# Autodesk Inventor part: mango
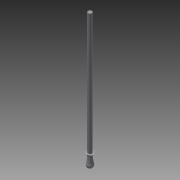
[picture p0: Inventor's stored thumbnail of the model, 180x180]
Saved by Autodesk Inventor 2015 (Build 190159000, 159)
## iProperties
Created: 2016-05
Part Number: mango
Material: Genérico
Document SubType Name: Modeling
Designer: ALEX
Density: 1 g/cm^3
Appearance: Valor por defecto
Author: ALEX
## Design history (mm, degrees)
sketch "Boceto1"
  geometry: C1 r 7.5 at (0, 0); 1 further point
  constraints: 1 centre point, 1 coincident
  dimensions: "d0" = 15 diameter of C1
extrude "Extrusión1" new body sketch "Boceto1" distance "d1" = 450; taper "d2" = 0 deg
node "Plano de trabajo1"
sketch "Boceto2"
  geometry: 1 further point
sketch "Boceto3"
  geometry: L1 (0, 0)-(0, -50); L2 (7.512, 0)-(13.518, 0); L3 (7.512, 0)-(0, 0); L4 (-7.5, 0)-(7.5, 0) reference; A1 r 12.288 centre (19.752, -10.589) between (13.518, 0) and (7.512, -11.676); A2 r 135.634 centre (143.021, -5.838) between (7.465, -10.448) and (10.266, -33.634); A3 r 12.288 centre (-19.752, -10.589) between (-7.512, -11.676) and (-7.465, -10.448); A4 r 135.634 centre (-143.021, -5.838) between (-7.488, -0.612) and (-7.512, 0); A5 r 11.402 centre (0, -38.598) between (0, -50) and (10.266, -33.634); A6 r 135.634 centre (-143.021, -5.838) between (-7.512, -11.676) and (-7.465, -10.448)
  constraints: 14 point on circle, 6 centre point, 6 end point, 4 symmetric about line, 1 collinear, 1 horizontal, 1 point on line, 1 vertical, 1 other
  dimensions: "d4" = 50 distance of L1.start L1.end
revolve "Revolución1" sketch "Boceto3" stored, may be unused: angle "d5" = 90 deg
fillet "Empalme1" dims "d6" = 2
node "Sólido1"
other parameters: "d3" = 0
